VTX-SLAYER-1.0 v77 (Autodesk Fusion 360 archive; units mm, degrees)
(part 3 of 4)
sketch "vtx-antenna_mount" plane through (0, 0, 32) normal (0, 0, -1) x axis (1, 0, 0)
  line L1 (-21.0607, 19.5622) -> (-27.6022, 26.6869)
  curve K1 (-9.6778, 20.9358) -> (-10.9746, 20.0338)
  curve K2 (21.4163, 20.9358) -> (22.7131, 20.0338)
  line L2 (34.4732, 21.3854) -> (32.7992, 19.5622)
  curve K3 (34.4732, 21.3854) -> (34.8613, 29.5821)
  curve K4 (34.4729, 47.5027) -> (34.8613, 50.4161)
  curve K5 (34.8613, 50.4161) -> (34.4732, 58.6128)
  line L3 (32.7992, 60.4361) -> (34.4732, 58.6128)
  curve K6 (21.4163, 59.0625) -> (22.7131, 59.9644)
  curve K7 (-9.6778, 59.0625) -> (-10.9746, 59.9644)
  line L4 (-27.6022, 53.3114) -> (-21.0607, 60.4361)
  line L5 (26.3392, 29.4991) -> (30.319, 29.4991)
  line L6 (30.319, 32.4991) -> (26.3392, 32.4991)
  line L7 (30.319, 50.4991) -> (26.3392, 50.4991)
  line L8 (26.3392, 47.4991) -> (30.319, 47.4991)
  line L9 (30.319, 29.4991) -> (26.3392, 29.4991)
  line L10 (26.3392, 32.4991) -> (30.319, 32.4991)
  line L11 (30.319, 47.4991) -> (26.3392, 47.4991)
  line L12 (26.3392, 50.4991) -> (30.319, 50.4991)
  curve K8 (34.47, 47.4768) -> (31.9524, 44.1894)
  curve K9 (34.4729, 47.5027) -> (34.8613, 50.4161)
  curve K10 (34.8613, 50.4161) -> (34.4732, 58.6128)
  line L13 (34.4732, 58.6128) -> (32.7992, 60.4361)
  curve K11 (22.7131, 59.9644) -> (21.4163, 59.0625)
  curve K12 (34.4732, 21.3854) -> (34.8613, 29.5821)
  line L14 (32.7992, 19.5622) -> (34.4732, 21.3854)
  curve K13 (21.4163, 20.9358) -> (22.7131, 20.0338)
  line L15 (19.3693, 59.1611) -> (19.3693, 25.3947)
  line L16 (42, 39.9991) -> (17.9297, 39.9991)
  line L17 (34.47, 32.5215) -> (34.47, 47.4768)
  line L18 (34.47, 47.4768) -> (34.6901, 56.5235)
  line L19 (34.47, 32.5215) -> (34.6901, 23.4747)
  curve K14 (5.8693, 25.0204) -> (-1.6863, 24.3869)
  curve K15 (5.8693, 54.9778) -> (-1.6863, 55.6114)
  curve K16 (-13.7829, 18.3445) -> (-21.0607, 19.5622)
  curve K17 (-10.9746, 20.0338) -> (-13.7829, 18.3445)
  curve K18 (5.8693, 25.0204) -> (13.4249, 24.3869)
  curve K19 (22.7131, 20.0338) -> (25.5215, 18.3445)
  curve K20 (32.7992, 19.5622) -> (25.5215, 18.3445)
  curve K21 (32.7992, 60.4361) -> (25.5215, 61.6537)
  curve K22 (22.7131, 59.9644) -> (25.5215, 61.6537)
  curve K23 (5.8693, 54.9778) -> (13.4249, 55.6114)
  curve K24 (-10.9746, 59.9644) -> (-13.7829, 61.6537)
  curve K25 (-13.7829, 61.6537) -> (-21.0607, 60.4361)
  curve K26 (-13.7829, 18.3445) -> (-10.9746, 20.0338)
  curve K27 (25.5215, 18.3445) -> (32.7992, 19.5622)
  curve K28 (-9.4692, 21.0728) -> (-9.6778, 20.9358)
  curve K29 (-1.6863, 24.3869) -> (-1.7709, 24.37)
  curve K30 (13.4249, 24.3869) -> (13.5094, 24.37)
  curve K31 (21.2077, 21.0728) -> (21.4163, 20.9358)
  curve K32 (21.2077, 58.9255) -> (21.4163, 59.0625)
  curve K33 (13.4249, 55.6114) -> (13.5094, 55.6283)
  curve K34 (-1.6863, 55.6114) -> (-1.7709, 55.6283)
  curve K35 (-9.4692, 58.9255) -> (-9.6778, 59.0625)
  curve K36 (34.4729, 32.4955) -> (34.8613, 29.5821)
  curve K37 (34.47, 32.5215) -> (31.9524, 35.8089)
  line L20 (24.7082, 44.5019) -> (21.9057, 47.2714)
  line L21 (26.1937, 39.0527) -> (26.1937, 40.9455)
  line L22 (21.9057, 32.7269) -> (24.7082, 35.4963)
  line L23 (2.0745, 29.0204) -> (9.5861, 29.0204)
  line L24 (9.5861, 50.9778) -> (2.0745, 50.9778)
  curve K38 (-1.7709, 24.37) -> (-9.4692, 21.0728)
  curve K39 (13.5094, 24.37) -> (21.2077, 21.0728)
  line L25 (34.4729, 32.4955) -> (34.47, 32.5215)
  line L26 (34.47, 47.4768) -> (34.4729, 47.5027)
  curve K40 (13.5094, 55.6283) -> (21.2077, 58.9255)
  curve K41 (-1.7709, 55.6283) -> (-9.4692, 58.9255)
  line L27 (-9.3955, 28.8599) -> (-15.7249, 35.138)
  line L28 (10.9945, 32.4404) -> (7.2082, 36.196)
  line L29 (4.3798, 36.1845) -> (0.6546, 32.4289)
  line L30 (7.2082, 43.8022) -> (10.9945, 47.5578)
  line L31 (0.6546, 47.5694) -> (4.3798, 43.8137)
  line L32 (-3.666, 33.753) -> (-0.2646, 37.1822)
  line L33 (-12.0826, 37.1592) -> (-8.5664, 33.6715)
  line L34 (-8.5664, 46.3268) -> (-12.0826, 42.839)
  line L35 (-0.2646, 42.816) -> (-3.666, 46.2452)
  line L36 (15.3511, 46.2451) -> (11.9172, 42.839)
  line L37 (11.9172, 37.1592) -> (15.3511, 33.7531)
  line L38 (-15.7249, 44.8602) -> (-9.3955, 51.1383)
  arc A1 centre (-25.3924, 51.2824) radius 3 clockwise from (-26.8824, 48.6786) to (-27.6022, 53.3114)
  arc A2 centre (-31.849, 39.9991) radius 10 clockwise from (-26.8824, 48.6786) to (-26.8824, 31.3197)
  arc A3 centre (-25.3924, 28.7158) radius 3 clockwise from (-27.6022, 26.6869) to (-26.8824, 31.3197)
  circle C1 centre (-18.1307, 23.4991) radius 1.55
  circle C2 centre (-18.1307, 56.4991) radius 1.55
  arc A4 centre (26.3392, 30.9991) radius 1.5 clockwise from (26.3392, 29.4991) to (26.3392, 32.4991)
  arc A5 centre (30.319, 30.9991) radius 1.5 clockwise from (30.319, 32.4991) to (30.319, 29.4991)
  arc A6 centre (30.319, 48.9991) radius 1.5 clockwise from (30.319, 50.4991) to (30.319, 47.4991)
  arc A7 centre (26.3392, 48.9991) radius 1.5 clockwise from (26.3392, 47.4991) to (26.3392, 50.4991)
  arc A8 centre (26.3392, 30.9991) radius 1.5 clockwise from (26.3392, 29.4991) to (26.3392, 32.4991)
  arc A9 centre (30.319, 30.9991) radius 1.5 clockwise from (30.319, 32.4991) to (30.319, 29.4991)
  arc A10 centre (26.3392, 48.9991) radius 1.5 clockwise from (26.3392, 47.4991) to (26.3392, 50.4991)
  arc A11 centre (30.319, 48.9991) radius 1.5 clockwise from (30.319, 50.4991) to (30.319, 47.4991)
  arc A12 centre (33.5931, 39.9991) radius 4.5 clockwise from (31.9524, 35.8089) to (31.9524, 44.1894)
  circle C3 centre (29.8693, 56.4991) radius 4.8209
  circle C4 centre (29.8693, 56.4991) radius 3.025
  circle C5 centre (29.8693, 23.4991) radius 4.8209
  circle C6 centre (29.8693, 23.4991) radius 3.025
  arc A13 centre (50.9984, 39.9992) radius 31.6291 clockwise from (26.0429, 20.5666) to (26.0525, 59.4441)
  circle C7 centre (29.8693, 56.4991) radius 1.55
  circle C8 centre (29.8693, 23.4991) radius 1.55
  circle C9 centre (15.8693, 49.9991) radius 1.05
  circle C10 centre (-4.1307, 49.9991) radius 1.05
  circle C11 centre (15.8693, 29.9991) radius 1.05
  circle C12 centre (-4.1307, 29.9991) radius 1.05
  arc A14 centre (15.8693, 29.9991) radius 3.25 clockwise from (16.4204, 33.202) to (17.9117, 32.5272)
  arc A15 centre (-4.1307, 29.9991) radius 3.25 clockwise from (-5.3387, 33.0163) to (-4.7221, 33.1949)
  arc A16 centre (-18.1307, 23.4991) radius 5.55 clockwise from (-18.4728, 29.0386) to (-13.5782, 26.6736)
  arc A17 centre (-31.849, 39.9991) radius 14 clockwise from (-18.9728, 34.5032) to (-20.2526, 32.1553)
  arc A18 centre (-18.1307, 56.4991) radius 5.55 clockwise from (-13.5782, 53.3246) to (-18.4728, 50.9597)
  arc A19 centre (-4.1307, 49.9991) radius 3.25 clockwise from (-4.7221, 46.8034) to (-5.3387, 46.9819)
  arc A20 centre (15.8693, 49.9991) radius 3.25 clockwise from (17.9117, 47.4711) to (16.4204, 46.7962)
  arc A21 centre (-10.8039, 27.4399) radius 2 clockwise from (-9.3955, 28.8599) to (-10.177, 25.5408)
  arc A22 centre (-11.1174, 28.3895) radius 3 clockwise from (-10.177, 25.5408) to (-13.5782, 26.6736)
  arc A23 centre (-18.596, 31.0348) radius 2 clockwise from (-18.4728, 29.0386) to (-20.2526, 32.1553)
  arc A24 centre (-17.1334, 33.7181) radius 2 clockwise from (-18.9728, 34.5032) to (-15.7249, 35.138)
  arc A25 centre (9.5861, 31.0204) radius 2 clockwise from (10.9945, 32.4404) to (9.5861, 29.0204)
  arc A26 centre (2.0745, 31.0204) radius 2 clockwise from (2.0745, 29.0204) to (0.6546, 32.4289)
  arc A27 centre (5.7998, 34.7761) radius 2 clockwise from (4.3798, 36.1845) to (7.2082, 36.196)
  arc A28 centre (2.0745, 48.9778) radius 2 clockwise from (0.6546, 47.5694) to (2.0745, 50.9778)
  arc A29 centre (9.5861, 48.9778) radius 2 clockwise from (9.5861, 50.9778) to (10.9945, 47.5578)
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  point P53 (34.47, 47.4768)
  point P68 (34.47, 47.4768)
  point P71 (34.6901, 56.5235)
  point P72 (34.47, 47.4768)
  point P75 (34.6901, 23.4747)
  point P76 (34.47, 32.5215)
  point P78 (26.0429, 20.5666)
  point P77 (26.0525, 59.4441)
  perpendicular L15 L16
  coincident P53 P68
  tangent L3 C3
  coincident C3 P71
  coincident P53 P72
  symmetric L16 C3 C5
  symmetric L16 C4 C6
  symmetric L16 P71 P75
  symmetric L16 P72 P76
  tangent L15 A13
  coincident C5 P78
  coincident C3 P77
  dimension "d1057" diameter C4 = 6.05
work_plane "WorkPlane15" RotateAngle -45
sketch "vtx-antenna-hole" plane through (20.4594, -39.9991, 30.9099) normal (0.7071, 0, 0.7071) x axis (0, -1, 0)
  line L1 (0, 25) -> (0, -3.5)
  circle C1 centre (0, 11.4101) radius 4.5
  circle C2 centre (0, 11.4101) radius 2.5
  concentric C1 C2
  vertical L1
  dimension "d882" diameter C1 = 9
  dimension "d883" diameter C2 = 5
extrude "Extrude127" new body sketch "vtx-antenna-hole" profile of C1 C2 along normal blind 25 bodies "vtx-antenna-mount"
extrude "Extrude128" add sketch "vtx-antenna_mount" along normal blind 3
extrude "Extrude129" cut sketch "vtx-antenna-hole" profile of C2 along normal blind 47
work_plane "WorkPlane18" RotateAngle -90
sketch "Sketch92" plane through (19.3693, -39.9991, 29) normal (1, 0, 0) x axis (0, 1, 0)
  line L1 (-6.5, 0) -> (6.5, 0)
  line L2 (-6.5, -10.2079) -> (-6.5, 0)
  line L3 (6.5, -10.2079) -> (-6.5, -10.2079)
  line L4 (6.5, 0) -> (6.5, -10.2079)
  line L5 (-8.0736, 0) -> (-19.445, 0)
  line L6 (19.4325, 0) -> (8.0736, 0)
  horizontal L1
  vertical L2
  horizontal L3
  vertical L4
extrude "Extrude130" cut sketch "Sketch92" profile of L1 L2 L3 L4 along normal blind 29
fillet "Fillet99" radius 0.8
fillet "Fillet100" radius 4
fillet "Fillet101" radius 0.7
fillet "Fillet108" radius 3
fillet "Fillet109" radius 7
sketch "Sketch93" plane through (0, 0, 29) normal (0, 0, -1) x axis (1, 0, 0)
  line L1 (26.3392, 47.4991) -> (30.319, 47.4991)
  line L2 (30.319, 50.4991) -> (26.3392, 50.4991)
  line L3 (34.47, 47.4768) -> (34.47, 47.2361)
  line L4 (34.4729, 47.5027) -> (34.47, 47.4768)
  curve K1 (34.8613, 50.4161) -> (34.4729, 47.5027)
  curve K2 (34.4732, 58.6128) -> (34.8613, 50.4161)
  line L5 (33.4204, 59.7595) -> (34.4732, 58.6128)
  line L6 (24.7082, 44.5019) -> (23.7608, 45.4381)
  line L7 (26.1937, 39.0527) -> (26.1937, 40.9455)
  line L8 (23.7609, 34.5602) -> (24.7082, 35.4963)
  line L9 (34.4732, 21.3854) -> (33.4204, 20.2387)
  curve K3 (34.8613, 29.5821) -> (34.4732, 21.3854)
  curve K4 (34.4729, 32.4955) -> (34.8613, 29.5821)
  line L10 (34.47, 32.5215) -> (34.4729, 32.4955)
  line L11 (34.47, 32.7621) -> (34.47, 32.5215)
  line L12 (26.3392, 29.4991) -> (30.319, 29.4991)
  line L13 (30.319, 32.4991) -> (26.3392, 32.4991)
  curve K5 (34.47, 32.7621) -> (36.774, 35.7482)
  curve K6 (36.774, 44.25) -> (34.47, 47.2361)
  arc A1 centre (29.8693, 56.4991) radius 4.8209 clockwise from (26.0525, 59.4441) to (33.4204, 59.7595)
  arc A2 centre (19.5063, 39.9991) radius 7.6719 clockwise from (20.3034, 47.6295) to (20.3035, 32.3688)
  closed curve K7 centre (35.4859, 39.9991)
  arc A3 centre (30.319, 48.9991) radius 1.5 clockwise from (30.319, 50.4991) to (30.319, 47.4991)
  arc A4 centre (26.3392, 48.9991) radius 1.5 clockwise from (26.3392, 47.4991) to (26.3392, 50.4991)
  circle C1 centre (29.8693, 56.4991) radius 3.025
  arc A5 centre (50.9984, 39.9992) radius 31.6291 clockwise from (26.0429, 20.5666) to (22.3382, 26.6202)
  arc A6 centre (21.1937, 40.9455) radius 5 clockwise from (24.7082, 44.5019) to (26.1937, 40.9455)
  arc A7 centre (21.1937, 39.0527) radius 5 clockwise from (26.1937, 39.0527) to (24.7082, 35.4963)
  arc A8 centre (29.8693, 23.4991) radius 4.8209 clockwise from (33.4204, 20.2387) to (26.0429, 20.5666)
  closed curve K8 centre (34.6859, 39.9991)
  circle C2 centre (29.8693, 23.4991) radius 3.025
  arc A9 centre (30.319, 30.9991) radius 1.5 clockwise from (30.319, 32.4991) to (30.319, 29.4991)
  arc A10 centre (26.3392, 30.9991) radius 1.5 clockwise from (26.3392, 29.4991) to (26.3392, 32.4991)
  arc A11 centre (28.6812, 29.5812) radius 7 clockwise from (22.3382, 26.6202) to (23.7609, 34.5602)
  arc A12 centre (50.9984, 39.9992) radius 31.6291 clockwise from (22.3382, 53.3781) to (26.0525, 59.4441)
  arc A13 centre (28.6811, 50.4171) radius 7 clockwise from (23.7608, 45.4381) to (22.3382, 53.3781)
sketch "25.6 mount" plane through (0, 0, 7) normal (0, 0, 1) x axis (-1, 0, 0)
  curve K1 (2.0117, 48.6726) -> (-5.8693, 49.9885)
  curve K2 (11.053, 39.9991) -> (5.0002, 47.6552)
  curve K3 (5.0002, 32.3431) -> (11.053, 39.9991)
  curve K4 (-5.8693, 30.0098) -> (2.0117, 31.3257)
  curve K5 (-13.7502, 31.3257) -> (-5.8693, 30.0098)
  curve K6 (-15.8119, 47.4998) -> (-15.9266, 32.4985)
  curve K7 (-5.8693, 49.9885) -> (-13.7502, 48.6726)
  curve K8 (-34.4732, 21.3854) -> (-34.8613, 29.5821)
  line L1 (-32.7992, 19.5622) -> (-34.4732, 21.3854)
  curve K9 (-32.7992, 19.5622) -> (-25.5215, 18.3445)
  curve K10 (-22.7131, 20.0338) -> (-25.5215, 18.3445)
  curve K11 (-21.4163, 20.9358) -> (-22.7131, 20.0338)
  curve K12 (-21.2077, 21.0728) -> (-21.4163, 20.9358)
  curve K13 (-13.5094, 24.37) -> (-21.2077, 21.0728)
  curve K14 (-13.4249, 24.3869) -> (-13.5094, 24.37)
  curve K15 (-5.8693, 25.0204) -> (-13.4249, 24.3869)
  curve K16 (-5.8693, 25.0204) -> (1.6863, 24.3869)
  curve K17 (1.6863, 24.3869) -> (1.7709, 24.37)
  curve K18 (9.4692, 21.0728) -> (1.7709, 24.37)
  curve K19 (9.4692, 21.0728) -> (9.6778, 20.9358)
  curve K20 (9.6778, 20.9358) -> (10.9746, 20.0338)
  curve K21 (10.9746, 20.0338) -> (13.7829, 18.3445)
  curve K22 (13.7829, 18.3445) -> (21.0607, 19.5622)
  line L2 (21.7601, 20.324) -> (21.0607, 19.5622)
  curve K23 (23.3399, 24.4614) -> (21.2218, 28.4813)
  curve K24 (14.991, 38.4401) -> (21.2218, 28.4813)
  curve K25 (14.9178, 39.9991) -> (14.991, 38.4401)
  curve K26 (14.9178, 39.9991) -> (14.991, 41.5582)
  curve K27 (14.991, 41.5582) -> (21.2218, 51.5169)
  curve K28 (21.2218, 51.5169) -> (23.3399, 55.5369)
  line L3 (21.0607, 60.4361) -> (21.7601, 59.6743)
  curve K29 (13.7829, 61.6537) -> (21.0607, 60.4361)
  curve K30 (10.9746, 59.9644) -> (13.7829, 61.6537)
  curve K31 (9.6778, 59.0625) -> (10.9746, 59.9644)
  curve K32 (9.4692, 58.9255) -> (9.6778, 59.0625)
  curve K33 (1.7709, 55.6283) -> (9.4692, 58.9255)
  curve K34 (1.6863, 55.6114) -> (1.7709, 55.6283)
  curve K35 (-5.8693, 54.9778) -> (1.6863, 55.6114)
  curve K36 (-5.8693, 54.9778) -> (-13.4249, 55.6114)
  curve K37 (-13.4249, 55.6114) -> (-13.5094, 55.6283)
  curve K38 (-21.2077, 58.9255) -> (-13.5094, 55.6283)
  curve K39 (-21.2077, 58.9255) -> (-21.4163, 59.0625)
  curve K40 (-21.4163, 59.0625) -> (-22.7131, 59.9644)
  curve K41 (-22.7131, 59.9644) -> (-25.5215, 61.6537)
  curve K42 (-32.7992, 60.4361) -> (-25.5215, 61.6537)
  line L4 (-34.4732, 58.6128) -> (-32.7992, 60.4361)
  curve K43 (-34.8613, 50.4161) -> (-34.4732, 58.6128)
  curve K44 (-34.4729, 47.5027) -> (-34.8613, 50.4161)
  curve K45 (-34.2161, 44.4991) -> (-34.4729, 47.5027)
  curve K46 (-34.0919, 41.4991) -> (-34.2161, 44.4991)
  curve K47 (-34.0692, 39.9991) -> (-34.0919, 41.4991)
  curve K48 (-34.0919, 38.4991) -> (-34.0692, 39.9991)
  curve K49 (-34.0919, 38.4991) -> (-34.2161, 35.4991)
  curve K50 (-34.4729, 32.4955) -> (-34.2161, 35.4991)
  curve K51 (-34.4729, 32.4955) -> (-34.8613, 29.5821)
  line L5 (-26.3392, 32.4991) -> (-30.319, 32.4991)
  line L6 (-30.319, 29.4991) -> (-26.3392, 29.4991)
  line L7 (-23.7522, 38.4991) -> (-30.319, 38.4991)
  line L8 (-30.319, 35.4991) -> (-23.7522, 35.4991)
  line L9 (-26.3392, 50.4991) -> (-30.319, 50.4991)
  line L10 (-30.319, 47.4991) -> (-26.3392, 47.4991)
  line L11 (-23.7522, 44.4991) -> (-30.319, 44.4991)
  line L12 (-30.319, 41.4991) -> (-23.7522, 41.4991)
  line L13 (-15.8693, 49.9991) -> (4.1307, 29.9991)
  line L14 (-15.8693, 29.9991) -> (4.1307, 49.9991)
  line L15 (-5.8693, 9.9991) -> (-5.8693, 39.9991)
  line L16 (-35.8693, 39.9991) -> (-5.8693, 39.9991)
  line L17 (-5.8693, 69.9991) -> (-5.8693, 39.9991)
  line L18 (24.1307, 39.9991) -> (-5.8693, 39.9991)
  line L19 (-23.9712, 39.9991) -> (-5.8693, 58.1011)
  line L20 (-5.8693, 21.8972) -> (-23.9712, 39.9991)
  line L21 (-5.8693, 21.8972) -> (12.2327, 39.9991)
  line L22 (0.3923, 24.6107) -> (-4.104, 20.127)
  line L23 (-12.109, 24.6139) -> (-7.6395, 20.1319)
  line L24 (0.3923, 55.3876) -> (-4.104, 59.8713)
  line L25 (-12.109, 55.3843) -> (-7.6395, 59.8663)
  arc A1 centre (4.1307, 49.9991) radius 2.5 clockwise from (5.0002, 47.6552) to (2.0117, 48.6726)
  arc A2 centre (4.1307, 29.9991) radius 2.5 clockwise from (2.0117, 31.3257) to (5.0002, 32.3431)
  arc A3 centre (-15.8693, 29.9991) radius 2.5 clockwise from (-15.9266, 32.4985) to (-13.7502, 31.3257)
  arc A4 centre (-15.8693, 49.9991) radius 2.5 clockwise from (-13.7502, 48.6726) to (-15.8119, 47.4998)
  arc A5 centre (17.3404, 24.3819) radius 6 clockwise from (23.3399, 24.4614) to (21.7601, 20.324)
  arc A6 centre (17.3404, 55.6164) radius 6 clockwise from (21.7601, 59.6743) to (23.3399, 55.5369)
  arc A7 centre (-30.319, 30.9991) radius 1.5 clockwise from (-30.319, 29.4991) to (-30.319, 32.4991)
  arc A8 centre (-26.3392, 30.9991) radius 1.5 clockwise from (-26.3392, 32.4991) to (-26.3392, 29.4991)
  arc A9 centre (-23.7522, 36.9991) radius 1.5 clockwise from (-23.7522, 38.4991) to (-23.7522, 35.4991)
  arc A10 centre (-30.319, 36.9991) radius 1.5 clockwise from (-30.319, 35.4991) to (-30.319, 38.4991)
  arc A11 centre (-26.3392, 48.9991) radius 1.5 clockwise from (-26.3392, 50.4991) to (-26.3392, 47.4991)
  arc A12 centre (-30.319, 48.9991) radius 1.5 clockwise from (-30.319, 47.4991) to (-30.319, 50.4991)
  circle C1 centre (-29.8693, 56.4991) radius 2.55
  circle C2 centre (18.1307, 56.4991) radius 2.55
  circle C3 centre (-29.8693, 23.4991) radius 2.55
  circle C4 centre (18.1307, 23.4991) radius 2.55
  circle C5 centre (4.1307, 49.9991) radius 1.05
  circle C6 centre (-15.8693, 49.9991) radius 1.05
  circle C7 centre (4.1307, 29.9991) radius 1.05
  circle C8 centre (-15.8693, 29.9991) radius 1.05
  arc A13 centre (-30.319, 42.9991) radius 1.5 clockwise from (-30.319, 41.4991) to (-30.319, 44.4991)
  arc A14 centre (-23.7522, 42.9991) radius 1.5 clockwise from (-23.7522, 44.4991) to (-23.7522, 41.4991)
  circle C9 centre (-5.8693, 21.8972) radius 1.05
  circle C10 centre (-5.8693, 58.1011) radius 1.05
  circle C11 centre (12.2327, 39.9991) radius 1.05
  circle C12 centre (-23.9712, 39.9991) radius 1.05
  circle C13 centre (-5.8693, 21.8972) radius 2.5
  circle C14 centre (-5.8693, 58.1011) radius 2.5
  circle C15 centre (12.2327, 39.9991) radius 4
  circle C16 centre (-23.9712, 39.9991) radius 4
  circle C17 centre (-28.581, 42.9991) radius 1.5
  circle C18 centre (-28.581, 36.9991) radius 1.5
  point P9 (4.1307, 29.9991)
  point P97 (4.1307, 29.9991)
  point P16 (-15.8693, 49.9991)
  point P98 (-15.8693, 49.9991)
  point P5 (4.1307, 49.9991)
  point P99 (4.1307, 49.9991)
  point P13 (-15.8693, 29.9991)
  point P100 (-15.8693, 29.9991)
  point P101 (-5.8693, 39.9991)
  point P106 (-5.8693, 21.8972)
  point P107 (-5.8693, 58.1011)
  point P108 (12.2327, 39.9991)
  point P109 (-23.9712, 39.9991)
  point P110 (-5.8693, 58.1011)
  point P111 (-23.9712, 39.9991)
  point P112 (-23.9712, 39.9991)
  point P113 (-5.8693, 21.8972)
  point P114 (12.2327, 39.9991)
  point P115 (-5.8693, 21.8972)
  point P118 (-23.9712, 39.9991)
  point P121 (-4.104, 20.127)
  point P122 (0.3923, 24.6107)
  point P123 (-7.6395, 20.1319)
  point P124 (-12.109, 24.6139)
  point P125 (-4.104, 59.8713)
  point P126 (0.3923, 55.3876)
  point P127 (-7.6395, 59.8663)
  point P128 (-12.109, 55.3843)
  point P119 (-28.581, 42.9991)
  point P120 (-28.581, 36.9991)
  coincident P9 P97
  coincident P16 P98
  coincident P5 P99
  coincident P13 P100
  midpoint L14 P101
  vertical L15
  perpendicular L15 L16
  perpendicular L16 L17
  perpendicular L15 L18
  coincident L15 P106
  coincident L17 P107
  coincident L18 P108
  coincident L16 P109
  coincident P107 P110
  coincident P109 P111
  coincident P109 P112
  coincident P106 P113
  coincident P108 P114
  coincident P113 P115
  concentric C10 C14
  concentric C11 C15
  coincident P111 P118
  tangent L11 C17
  tangent L8 C18
  coincident C13 P121
  coincident K16 P122
  tangent C13 L22
  coincident C13 P123
  coincident K15 P124
  tangent C13 L23
  perpendicular L22 L23
  symmetric L16 P121 P125
  symmetric L16 P122 P126
  symmetric L16 P123 P127
  symmetric L16 P124 P128
  tangent L7 C18
  tangent L12 C17
  vertical P119 P120
  tangent C16 C18
  dimension "d1130" diameter C9 = 2.1
  dimension "d1131" diameter C10 = 2.1
  dimension "d1132" diameter C11 = 2.1
  dimension "d1133" diameter C12 = 2.1
  dimension "d1138" distance P107 P109 = 25.6
  dimension "d1139" angle L17 L19 = 45
  dimension "d1140" distance P106 P109 = 25.6
  dimension "d1141" distance P113 P114 = 25.6
  dimension "d1142" diameter C13 = 5
  dimension "d1143" diameter C14 = 5
  dimension "d1144" diameter C15 = 8
  dimension "d1145" diameter C16 = 8
extrude "Extrude133" cut sketch "25.6 mount" profile of C11 C12 against normal blind 6
extrude "Extrude134" add sketch "25.6 mount" profile of K2 K3 K15 K16 K24 K25 K26 K27 K35 K36 L7 A9 L8 L11 A14 L12 C9 C10 C13 C14 C15 C16 C17 C18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 against normal blind 2
extrude "Extrude135" cut sketch "25.6 mount" profile of C11 C12 against normal blind 2
fillet "Fillet110" radius 3
extrude "Extrude136" cut sketch "25.6 mount" profile of C11 C12 against normal blind 12
sketch "Sketch95" plane through (0, 0, -2) normal (0, 0, -1) x axis (1, 0, 0)
  curve K1 (32.9603, 51.5169) -> (35.0785, 55.5369)
  line L1 (32.7992, 60.4361) -> (33.4986, 59.6743)
  curve K2 (32.7992, 60.4361) -> (25.5215, 61.6537)
  curve K3 (22.7131, 59.9644) -> (25.5215, 61.6537)
  curve K4 (21.4163, 59.0625) -> (22.7131, 59.9644)
  curve K5 (13.5094, 55.6283) -> (21.4163, 59.0625)
  curve K6 (13.4249, 55.6114) -> (13.5094, 55.6283)
  curve K7 (5.8693, 54.9778) -> (13.4249, 55.6114)
  curve K8 (-1.6863, 55.6114) -> (5.8693, 54.9778)
  curve K9 (-1.7709, 55.6283) -> (-1.6863, 55.6114)
  curve K10 (-9.6778, 59.0625) -> (-1.7709, 55.6283)
  curve K11 (-10.9746, 59.9644) -> (-9.6778, 59.0625)
  curve K12 (-13.7829, 61.6537) -> (-10.9746, 59.9644)
  curve K13 (-13.7829, 61.6537) -> (-21.0607, 60.4361)
  line L2 (-32.5504, 47.922) -> (-21.0607, 60.4361)
  line L3 (-34.1307, 36.1341) -> (-34.1307, 43.8641)
  line L4 (-21.0607, 19.5622) -> (-32.5504, 32.0762)
  curve K14 (-13.7829, 18.3445) -> (-21.0607, 19.5622)
  curve K15 (-13.7829, 18.3445) -> (-10.9746, 20.0338)
  curve K16 (-10.9746, 20.0338) -> (-9.6778, 20.9358)
  curve K17 (-9.6778, 20.9358) -> (-1.7709, 24.37)
  curve K18 (-1.7709, 24.37) -> (-1.6863, 24.3869)
  curve K19 (-1.6863, 24.3869) -> (5.8693, 25.0204)
  curve K20 (5.8693, 25.0204) -> (13.4249, 24.3869)
  curve K21 (13.4249, 24.3869) -> (13.5094, 24.37)
  curve K22 (13.5094, 24.37) -> (21.4163, 20.9358)
  curve K23 (21.4163, 20.9358) -> (22.7131, 20.0338)
  curve K24 (22.7131, 20.0338) -> (25.5215, 18.3445)
  curve K25 (32.7992, 19.5622) -> (25.5215, 18.3445)
  line L5 (33.4986, 20.324) -> (32.7992, 19.5622)
  curve K26 (35.0785, 24.4614) -> (32.9603, 28.4813)
  curve K27 (32.9603, 28.4813) -> (26.7295, 38.4401)
  curve K28 (26.7295, 38.4401) -> (26.6564, 39.9991)
  curve K29 (26.7295, 41.5582) -> (26.6564, 39.9991)
  curve K30 (32.9603, 51.5169) -> (26.7295, 41.5582)
  line L6 (-14.6007, 32.4991) -> (-25.1307, 32.4991)
  line L7 (-25.1307, 29.4991) -> (-14.6007, 29.4991)
  line L8 (-29.6307, 35.4991) -> (-12.0137, 35.4991)
  line L9 (-12.0137, 38.4991) -> (-29.6307, 38.4991)
  line L10 (-12.0137, 44.4991) -> (-29.6307, 44.4991)
  line L11 (-29.6307, 41.4991) -> (-12.0137, 41.4991)
  line L12 (-25.1307, 47.4991) -> (-14.6007, 47.4991)
  line L13 (-14.6007, 50.4991) -> (-25.1307, 50.4991)
  circle C1 centre (23.9712, 39.9991) radius 1.05
  circle C2 centre (-12.2327, 39.9991) radius 1.05
  arc A1 centre (29.079, 55.6164) radius 6 clockwise from (33.4986, 59.6743) to (35.0785, 55.5369)
  arc A2 centre (-28.1307, 43.8641) radius 6 clockwise from (-34.1307, 43.8641) to (-32.5504, 47.922)
  arc A3 centre (-28.1307, 36.1341) radius 6 clockwise from (-32.5504, 32.0762) to (-34.1307, 36.1341)
  arc A4 centre (29.079, 24.3819) radius 6 clockwise from (35.0785, 24.4614) to (33.4986, 20.324)
  circle C3 centre (29.8693, 23.4991) radius 1.55
  arc A5 centre (15.8693, 29.9991) radius 2.1 clockwise from (15.8711, 32.0991) to (15.8711, 27.8991)
  arc A6 centre (15.873, 29.9991) radius 2.1 clockwise from (15.8711, 27.8991) to (15.8711, 32.0991)
  circle C4 centre (-4.1307, 29.9991) radius 2.1
  circle C5 centre (-18.1307, 23.4991) radius 1.55
  arc A7 centre (-14.6007, 30.9991) radius 1.5 clockwise from (-14.6007, 32.4991) to (-14.6007, 29.4991)
  arc A8 centre (-25.1307, 30.9991) radius 1.5 clockwise from (-25.1307, 29.4991) to (-25.1307, 32.4991)
  arc A9 centre (-29.6307, 36.9991) radius 1.5 clockwise from (-29.6307, 35.4991) to (-29.6307, 38.4991)
  arc A10 centre (-12.0137, 36.9991) radius 1.5 clockwise from (-12.0137, 38.4991) to (-12.0137, 35.4991)
  circle C6 centre (5.8693, 39.9991) radius 3
  arc A11 centre (-12.0137, 42.9991) radius 1.5 clockwise from (-12.0137, 44.4991) to (-12.0137, 41.4991)
  arc A12 centre (-29.6307, 42.9991) radius 1.5 clockwise from (-29.6307, 41.4991) to (-29.6307, 44.4991)
  arc A13 centre (-25.1307, 48.9991) radius 1.5 clockwise from (-25.1307, 47.4991) to (-25.1307, 50.4991)
  arc A14 centre (-14.6007, 48.9991) radius 1.5 clockwise from (-14.6007, 50.4991) to (-14.6007, 47.4991)
  circle C7 centre (-18.1307, 56.4991) radius 1.55
  circle C8 centre (-4.1307, 49.9991) radius 2.1
  arc A15 centre (15.8693, 49.9991) radius 2.1 clockwise from (15.8711, 52.0991) to (15.8711, 47.8991)
  arc A16 centre (15.873, 49.9991) radius 2.1 clockwise from (15.8711, 47.8991) to (15.8711, 52.0991)
  circle C9 centre (29.8693, 56.4991) radius 1.55
  circle C10 centre (-12.2327, 39.9991) radius 2.1
  circle C11 centre (23.9712, 39.9991) radius 2.1
  circle C12 centre (-12.2327, 39.9991) radius 4
  circle C13 centre (23.9712, 39.9991) radius 4
  circle C14 centre (-16.8424, 42.9991) radius 1.5
  circle C15 centre (-16.8424, 36.9991) radius 1.5
  concentric C2 C10
  concentric C1 C11
  concentric C2 C12
  concentric C11 C13
  tangent L10 C14
  tangent L11 C14
  tangent C12 C14
  tangent L9 C15
  tangent L8 C15
  tangent C12 C15
  dimension "d1156" diameter C10 = 4.2
  dimension "d1157" diameter C11 = 4.2
  dimension "d1158" diameter C12 = 8
  dimension "d1159" diameter C13 = 8
extrude "Extrude137" add sketch "Sketch95" profile of K27 K28 K29 K30 L8 L9 A10 L10 A11 L11 C10 C12 C13 C14 C15 against normal blind 2
extrude "Extrude138" cut sketch "Sketch95" profile of C1 C2 L9 A10 A11 L11 C10 C11 against normal blind 2
fillet "Fillet111" radius 3
extrude "Extrude139" add sketch "25.6 mount" profile of K2 K3 K24 K25 K26 K27 L7 A9 A14 L12 C11 C12 C15 C16 against normal blind 4
extrude "Extrude140" cut sketch "25.6 mount" profile of K2 K3 K24 K25 K26 K27 L7 A9 A14 L12 C11 C12 C15 C16 against normal blind 2
fillet "Fillet112" radius 3
component_insert "Component Insert5"
component_insert "Component Insert6"
extrude "Extrude132" new body sketch "cam-mount-base" profile of C2 C4 along normal blind 25 bodies "standoff1", "standoff2"
copy_paste_bodies "CopyPasteBodies13"
move "Move24"
component_insert "Component Insert7"
joint "Assemble6" alignAngle 0 alignOffsetX 0 alignOffsetY 0 alignOffsetZ 0
component_insert "Component Insert8"
joint "Assemble7" alignAngle 0 alignOffsetX 0 alignOffsetY 0 alignOffsetZ 0
component_insert "Component Insert9"
component_insert "Component Insert10"
joint "Assemble8" alignAngle 0 alignOffsetX 0 alignOffsetY 0 alignOffsetZ 0
joint "Assemble9" alignAngle 0 alignOffsetX 0 alignOffsetY 0 alignOffsetZ 0
component_insert "Component Insert11"
component_insert "Component Insert12"
component_insert "Component Insert13"
component_insert "Component Insert14"
component_insert "Component Insert15"
joint "Assemble14" alignAngle 0 alignOffsetX 0 alignOffsetY 0 alignOffsetZ 0
component_insert "Component Insert16"
component_insert "Component Insert17"
component_insert "Component Insert18"
joint "Assemble15" alignAngle 0 alignOffsetX 0 alignOffsetY 0 alignOffsetZ 0
joint "Assemble16" alignAngle 0 alignOffsetX 0 alignOffsetY 0 alignOffsetZ 0
joint "Assemble17" alignAngle 0 alignOffsetX 0 alignOffsetY 0 alignOffsetZ 0
component_insert "Component Insert19"
component_insert "Component Insert20"
joint "Assemble18" alignAngle 0 alignOffsetX 0 alignOffsetY 0 alignOffsetZ 0
joint "Assemble19" alignAngle 0 alignOffsetX 0 alignOffsetY 0 alignOffsetZ 0
component_insert "Component Insert21"
component_insert "Component Insert22"
joint "Assemble20" alignAngle 0 alignOffsetX 0 alignOffsetY 0 alignOffsetZ 0
joint "Assemble21" alignAngle 0 alignOffsetX 0 alignOffsetY 0 alignOffsetZ 0
component_insert "Component Insert23"
component_insert "Component Insert24"
component_insert "Component Insert25"
component_insert "Component Insert26"
joint "Assemble22" alignAngle 0 alignOffsetX 0 alignOffsetY 0 alignOffsetZ 0
joint "Assemble23" alignAngle 0 alignOffsetX 0 alignOffsetY 0 alignOffsetZ 0
joint "Assemble24" alignAngle 0 alignOffsetX 0 alignOffsetY 0 alignOffsetZ 0
joint "Assemble25" alignAngle 0 alignOffsetX 0 alignOffsetY 0 alignOffsetZ 0
component_insert "Component Insert27"
component_insert "Component Insert28"
component_insert "Component Insert29"
joint "Assemble26" alignAngle 0 alignOffsetX 0 alignOffsetY 0 alignOffsetZ 0
joint "Assemble27" alignAngle 0 alignOffsetX 0 alignOffsetY 0 alignOffsetZ 0
joint "Assemble28" alignAngle 0 alignOffsetX 0 alignOffsetY 0 alignOffsetZ 0
joint "Assemble29" alignAngle 0 alignOffsetX 0 alignOffsetY 0 alignOffsetZ 0
joint "Assemble30" alignAngle 0 alignOffsetX 0 alignOffsetY 0 alignOffsetZ 0
joint "Assemble31" alignAngle 0 alignOffsetX 0 alignOffsetY 0 alignOffsetZ 0
joint "Assemble32" alignAngle 0 alignOffsetX 0 alignOffsetY 0 alignOffsetZ 0
component_from_bodies "Body->Comp11"
component_from_bodies "Body->Comp12"
component_from_bodies "Body->Comp13"
component_from_bodies "Body->Comp14"
component_from_bodies "Body->Comp15"
component_from_bodies "Body->Comp16"
component_from_bodies "Body->Comp17"
component_from_bodies "Body->Comp18"
component_from_bodies "Body->Comp19"
component_from_bodies "Body->Comp21"
component_from_bodies "Body->Comp22"
component_from_bodies "Body->Comp23"
component_from_bodies "Body->Comp24"
sketch "pressnut1" plane through (0, 0, 5.9) normal (0, 0, 1) x axis (-1, 0, 0)
  circle C1 centre (-29.8693, 23.4991) radius 1.55
  circle C2 centre (-29.8693, 23.4991) radius 2.25
extrude "Extrude124" new body sketch "pressnut1" along normal blind 0.7 bodies "pressnut1"
sketch "pressnut2" plane through (0, 0, 6.6) normal (0, 0, 1) x axis (-1, 0, 0)
  line L1 (-29.6425, 21.2606) -> (-29.8656, 20.8741)
  line L2 (-29.4194, 20.8741) -> (-29.8656, 20.8741)
  line L3 (-30.0883, 21.2598) -> (-29.8656, 20.8741)
  line L4 (-29.1966, 21.352) -> (-29.3373, 20.9286)
  line L5 (-29.6331, 21.2615) -> (-29.3373, 20.9286)
  line L6 (-28.7781, 21.5314) -> (-28.8308, 21.0883)
  line L7 (-29.1875, 21.3549) -> (-28.8308, 21.0883)
  line L8 (-28.4044, 21.7913) -> (-28.3667, 21.3467)
  line L9 (-28.7698, 21.536) -> (-28.3667, 21.3467)
  line L10 (-28.0906, 22.1212) -> (-27.9642, 21.6932)
  line L11 (-28.3972, 21.7975) -> (-27.9642, 21.6932)
  line L12 (-27.8496, 22.5074) -> (-27.6397, 22.1137)
  line L13 (-28.0848, 22.1287) -> (-27.6397, 22.1137)
  line L14 (-27.6913, 22.9343) -> (-27.4064, 22.5908)
  line L15 (-27.8454, 22.516) -> (-27.4064, 22.5908)
  line L16 (-27.6222, 23.3843) -> (-27.274, 23.1052)
  line L17 (-27.6889, 22.9435) -> (-27.274, 23.1052)
  line L18 (-27.6451, 23.8389) -> (-27.2478, 23.6357)
  line L19 (-27.6217, 23.3938) -> (-27.2478, 23.6357)
  line L20 (-27.759, 24.2797) -> (-27.329, 24.1606)
  line L21 (-27.6465, 23.8483) -> (-27.329, 24.1606)
  line L22 (-27.9593, 24.6885) -> (-27.5141, 24.6584)
  line L23 (-27.7623, 24.2886) -> (-27.5141, 24.6584)
  line L24 (-28.2379, 25.0486) -> (-27.7957, 25.1088)
  line L25 (-27.9644, 24.6966) -> (-27.7957, 25.1088)
  line L26 (-28.5832, 25.3453) -> (-28.1622, 25.4932)
  line L27 (-28.2444, 25.0555) -> (-28.1622, 25.4932)
  line L28 (-28.9811, 25.5664) -> (-28.5985, 25.796)
  line L29 (-28.591, 25.3507) -> (-28.5985, 25.796)
  line L30 (-29.4155, 25.7029) -> (-29.0869, 26.0048)
  line L31 (-28.9899, 25.5702) -> (-29.0869, 26.0048)
  line L32 (-29.8684, 25.7491) -> (-29.6073, 26.111)
  line L33 (-29.4248, 25.7048) -> (-29.6073, 26.111)
  line L34 (-30.3213, 25.7032) -> (-30.1384, 26.1103)
  line L35 (-29.8779, 25.7491) -> (-30.1384, 26.1103)
  line L36 (-30.7557, 25.5671) -> (-30.6585, 26.0026)
  line L37 (-30.3306, 25.7013) -> (-30.6585, 26.0026)
  line L38 (-31.1539, 25.3463) -> (-31.1463, 25.7925)
  line L39 (-30.7645, 25.5634) -> (-31.1463, 25.7925)
  line L40 (-31.4994, 25.0499) -> (-31.5819, 25.4885)
  line L41 (-31.1617, 25.3409) -> (-31.5819, 25.4885)
  line L42 (-31.7782, 24.69) -> (-31.9473, 25.103)
  line L43 (-31.506, 25.043) -> (-31.9473, 25.103)
  line L44 (-31.9789, 24.2814) -> (-32.2276, 24.6519)
  line L45 (-31.7833, 24.682) -> (-32.2276, 24.6519)
  line L46 (-32.0932, 23.8407) -> (-32.4114, 24.1536)
  line L47 (-31.9822, 24.2725) -> (-32.4114, 24.1536)
  line L48 (-32.1164, 23.3861) -> (-32.4911, 23.6285)
  line L49 (-32.0946, 23.8313) -> (-32.4911, 23.6285)
  line L50 (-32.0477, 22.936) -> (-32.4634, 23.098)
  line L51 (-32.1159, 23.3766) -> (-32.4634, 23.098)
  line L52 (-31.8897, 22.509) -> (-32.3296, 22.5841)
  line L53 (-32.0453, 22.9268) -> (-32.3296, 22.5841)
  line L54 (-31.6491, 22.1226) -> (-32.095, 22.1075)
  line L55 (-31.8855, 22.5005) -> (-32.095, 22.1075)
  line L56 (-31.3355, 21.7925) -> (-31.7694, 21.688)
  line L57 (-31.6432, 22.1151) -> (-31.7694, 21.688)
  line L58 (-30.962, 21.5323) -> (-31.3659, 21.3425)
  line L59 (-31.3283, 21.7863) -> (-31.3659, 21.3425)
  line L60 (-30.5437, 21.3526) -> (-30.9011, 21.0854)
  line L61 (-30.9537, 21.5277) -> (-30.9011, 21.0854)
  line L62 (-30.0978, 21.2608) -> (-30.3941, 20.9271)
  line L63 (-30.5346, 21.3497) -> (-30.3941, 20.9271)
  circle C1 centre (-29.8693, 23.4991) radius 1.55
  circle C2 centre (-29.8693, 23.4991) radius 2.25
  circle C3 centre (-29.8693, 23.4991) radius 2.625
  point P4 (-29.8656, 20.8741)
  point P5 (-29.6425, 21.2606)
  point P7 (-30.0883, 21.2598)
  concentric C1 C3
  horizontal L2
  coincident C3 P4
  coincident C2 P5
  coincident C2 P7
  dimension "d1044" diameter C3 = 5.25 (= "4.500 mm + 0.75 mm")
  dimension "d1045" angle L1 L2 = 60
  dimension "d1046" angle L1 L3 = 60
  dimension "d1048" C-Pattern1-Angle = 360
extrude "Extrude125" add sketch "pressnut2" profile of C1 C2 L1 L3 L4 L5 L6 L7 L8 L9 L10 L11 L12 L13 L14 L15 L16 L17 L18 L19 L20 L21 L22 L23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 along normal blind 0.4
sketch "pressnut3" plane through (0, 0, 7) normal (0, 0, 1) x axis (-1, 0, 0)
  line L1 (-29.8656, 20.8741) -> (-30.0883, 21.2598)
  line L2 (-29.6425, 21.2606) -> (-29.8656, 20.8741)
  line L3 (-29.3373, 20.9286) -> (-29.6331, 21.2615)
  line L4 (-29.1966, 21.352) -> (-29.3373, 20.9286)
  line L5 (-28.8308, 21.0883) -> (-29.1875, 21.3549)
  line L6 (-28.7781, 21.5314) -> (-28.8308, 21.0883)
  line L7 (-28.3667, 21.3467) -> (-28.7698, 21.536)
  line L8 (-28.4044, 21.7913) -> (-28.3667, 21.3467)
  line L9 (-27.9642, 21.6932) -> (-28.3972, 21.7975)
  line L10 (-28.0906, 22.1212) -> (-27.9642, 21.6932)
  line L11 (-27.6397, 22.1137) -> (-28.0848, 22.1287)
  line L12 (-27.8496, 22.5074) -> (-27.6397, 22.1137)
  line L13 (-27.4064, 22.5908) -> (-27.8454, 22.516)
  line L14 (-27.6913, 22.9343) -> (-27.4064, 22.5908)
  line L15 (-27.274, 23.1052) -> (-27.6889, 22.9435)
  line L16 (-27.6222, 23.3843) -> (-27.274, 23.1052)
  line L17 (-27.2478, 23.6357) -> (-27.6217, 23.3938)
  line L18 (-27.6451, 23.8389) -> (-27.2478, 23.6357)
  line L19 (-27.329, 24.1606) -> (-27.6465, 23.8483)
  line L20 (-27.759, 24.2797) -> (-27.329, 24.1606)
  line L21 (-27.5141, 24.6584) -> (-27.7623, 24.2886)
  line L22 (-27.9593, 24.6885) -> (-27.5141, 24.6584)
  line L23 (-27.7957, 25.1088) -> (-27.9644, 24.6966)
  line L24 (-28.2379, 25.0486) -> (-27.7957, 25.1088)
  line L25 (-28.1622, 25.4932) -> (-28.2444, 25.0555)
  line L26 (-28.5832, 25.3453) -> (-28.1622, 25.4932)
  line L27 (-28.5985, 25.796) -> (-28.591, 25.3507)
  line L28 (-28.9811, 25.5664) -> (-28.5985, 25.796)
  line L29 (-29.0869, 26.0048) -> (-28.9899, 25.5702)
  line L30 (-29.4155, 25.7029) -> (-29.0869, 26.0048)
  line L31 (-29.6073, 26.111) -> (-29.4248, 25.7048)
  line L32 (-29.8684, 25.7491) -> (-29.6073, 26.111)
  line L33 (-30.1384, 26.1103) -> (-29.8779, 25.7491)
  line L34 (-30.3213, 25.7032) -> (-30.1384, 26.1103)
  line L35 (-30.6585, 26.0026) -> (-30.3306, 25.7013)
  line L36 (-30.7557, 25.5671) -> (-30.6585, 26.0026)
  line L37 (-31.1463, 25.7925) -> (-30.7645, 25.5634)
  line L38 (-31.1539, 25.3463) -> (-31.1463, 25.7925)
  line L39 (-31.5819, 25.4885) -> (-31.1617, 25.3409)
  line L40 (-31.4994, 25.0499) -> (-31.5819, 25.4885)
  line L41 (-31.9473, 25.103) -> (-31.506, 25.043)
  line L42 (-31.7782, 24.69) -> (-31.9473, 25.103)
  line L43 (-32.2276, 24.6519) -> (-31.7833, 24.682)
  line L44 (-31.9789, 24.2814) -> (-32.2276, 24.6519)
  line L45 (-32.4114, 24.1536) -> (-31.9822, 24.2725)
  line L46 (-32.0932, 23.8407) -> (-32.4114, 24.1536)
  line L47 (-32.4911, 23.6285) -> (-32.0946, 23.8313)
  line L48 (-32.1164, 23.3861) -> (-32.4911, 23.6285)
  line L49 (-32.4634, 23.098) -> (-32.1159, 23.3766)
  line L50 (-32.0477, 22.936) -> (-32.4634, 23.098)
  line L51 (-32.3296, 22.5841) -> (-32.0453, 22.9268)
  line L52 (-31.8897, 22.509) -> (-32.3296, 22.5841)
  line L53 (-32.095, 22.1075) -> (-31.8855, 22.5005)
  line L54 (-31.6491, 22.1226) -> (-32.095, 22.1075)
  line L55 (-31.7694, 21.688) -> (-31.6432, 22.1151)
  line L56 (-31.3355, 21.7925) -> (-31.7694, 21.688)
  line L57 (-31.3659, 21.3425) -> (-31.3283, 21.7863)
  line L58 (-30.962, 21.5323) -> (-31.3659, 21.3425)
  line L59 (-30.9011, 21.0854) -> (-30.9537, 21.5277)
  line L60 (-30.5437, 21.3526) -> (-30.9011, 21.0854)
  line L61 (-30.3941, 20.9271) -> (-30.5346, 21.3497)
  line L62 (-30.0978, 21.2608) -> (-30.3941, 20.9271)
  circle C1 centre (-29.8693, 23.4991) radius 1.55
  arc A1 centre (-29.8693, 23.4991) radius 2.25 clockwise from (-30.0883, 21.2598) to (-30.0978, 21.2608)
  arc A2 centre (-29.8693, 23.4991) radius 2.25 clockwise from (-29.6331, 21.2615) to (-29.6425, 21.2606)
  arc A3 centre (-29.8693, 23.4991) radius 2.25 clockwise from (-29.1875, 21.3549) to (-29.1966, 21.352)
  arc A4 centre (-29.8693, 23.4991) radius 2.25 clockwise from (-28.7698, 21.536) to (-28.7781, 21.5314)
  arc A5 centre (-29.8693, 23.4991) radius 2.25 clockwise from (-28.3972, 21.7975) to (-28.4044, 21.7913)
  arc A6 centre (-29.8693, 23.4991) radius 2.25 clockwise from (-28.0848, 22.1287) to (-28.0906, 22.1212)
  arc A7 centre (-29.8693, 23.4991) radius 2.25 clockwise from (-27.8454, 22.516) to (-27.8496, 22.5074)
  arc A8 centre (-29.8693, 23.4991) radius 2.25 clockwise from (-27.6889, 22.9435) to (-27.6913, 22.9343)
  arc A9 centre (-29.8693, 23.4991) radius 2.25 clockwise from (-27.6217, 23.3938) to (-27.6222, 23.3843)
  arc A10 centre (-29.8693, 23.4991) radius 2.25 clockwise from (-27.6465, 23.8483) to (-27.6451, 23.8389)
  arc A11 centre (-29.8693, 23.4991) radius 2.25 clockwise from (-27.7623, 24.2886) to (-27.759, 24.2797)
  arc A12 centre (-29.8693, 23.4991) radius 2.25 clockwise from (-27.9644, 24.6966) to (-27.9593, 24.6885)
  arc A13 centre (-29.8693, 23.4991) radius 2.25 clockwise from (-28.2444, 25.0555) to (-28.2379, 25.0486)
  arc A14 centre (-29.8693, 23.4991) radius 2.25 clockwise from (-28.591, 25.3507) to (-28.5832, 25.3453)
  arc A15 centre (-29.8693, 23.4991) radius 2.25 clockwise from (-28.9899, 25.5702) to (-28.9811, 25.5664)
  arc A16 centre (-29.8693, 23.4991) radius 2.25 clockwise from (-29.4248, 25.7048) to (-29.4155, 25.7029)
  arc A17 centre (-29.8693, 23.4991) radius 2.25 clockwise from (-29.8779, 25.7491) to (-29.8684, 25.7491)
  arc A18 centre (-29.8693, 23.4991) radius 2.25 clockwise from (-30.3306, 25.7013) to (-30.3213, 25.7032)
  arc A19 centre (-29.8693, 23.4991) radius 2.25 clockwise from (-30.7645, 25.5634) to (-30.7557, 25.5671)
  arc A20 centre (-29.8693, 23.4991) radius 2.25 clockwise from (-31.1617, 25.3409) to (-31.1539, 25.3463)
  arc A21 centre (-29.8693, 23.4991) radius 2.25 clockwise from (-31.506, 25.043) to (-31.4994, 25.0499)
  arc A22 centre (-29.8693, 23.4991) radius 2.25 clockwise from (-31.7833, 24.682) to (-31.7782, 24.69)
  arc A23 centre (-29.8693, 23.4991) radius 2.25 clockwise from (-31.9822, 24.2725) to (-31.9789, 24.2814)
  arc A24 centre (-29.8693, 23.4991) radius 2.25 clockwise from (-32.0946, 23.8313) to (-32.0932, 23.8407)
  arc A25 centre (-29.8693, 23.4991) radius 2.25 clockwise from (-32.1159, 23.3766) to (-32.1164, 23.3861)
  arc A26 centre (-29.8693, 23.4991) radius 2.25 clockwise from (-32.0453, 22.9268) to (-32.0477, 22.936)
  arc A27 centre (-29.8693, 23.4991) radius 2.25 clockwise from (-31.8855, 22.5005) to (-31.8897, 22.509)
  arc A28 centre (-29.8693, 23.4991) radius 2.25 clockwise from (-31.6432, 22.1151) to (-31.6491, 22.1226)
  arc A29 centre (-29.8693, 23.4991) radius 2.25 clockwise from (-31.3283, 21.7863) to (-31.3355, 21.7925)
  arc A30 centre (-29.8693, 23.4991) radius 2.25 clockwise from (-30.9537, 21.5277) to (-30.962, 21.5323)
  arc A31 centre (-29.8693, 23.4991) radius 2.25 clockwise from (-30.5346, 21.3497) to (-30.5437, 21.3526)
  circle C2 centre (-29.8693, 23.4991) radius 3.05
  concentric C1 C2
  dimension "d1051" diameter C2 = 6.1
extrude "Extrude126" add sketch "pressnut3" along normal blind 1.3
copy_paste_bodies "CopyPasteBodies11"
move "Move22"
copy_paste_bodies "CopyPasteBodies12"
move "Move23"
component_from_bodies "Body->Comp25"
component_from_bodies "Body->Comp26"
component_from_bodies "Body->Comp27"
component_from_bodies "Body->Comp28"
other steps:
base_feature "Base Feature1" bodies "arm-fr"
base_feature "Base Feature1" bodies "arm-rr"
base_feature "Base Feature1" bodies "pressnut1"
base_feature "Base Feature1" bodies "pressnut2"
base_feature "Base Feature1" bodies "pressnut4"
base_feature "Base Feature1" bodies "pressnut5"
base_feature "Base Feature1" bodies "arm-fl (1)"
base_feature "Base Feature1" bodies "arm-rl"
base_feature "Base Feature1" bodies "m-center"
base_feature "Base Feature1" bodies "m-bottom"
base_feature "Base Feature1" bodies "m-top"
base_feature "Base Feature1" bodies "top (1)"
base_feature "Base Feature1" bodies "cam-mount"
base_feature "Base Feature1" bodies "standoff1 (1)"
base_feature "Base Feature1" bodies "standoff2 (1)"
base_feature "Base Feature1" bodies "standoff1"
base_feature "Base Feature1" bodies "standoff2"
base_feature "Base Feature9" bodies "m-bottom", "m-top"
base_feature "Base Feature11" bodies "pressnut", "pressnut2"
base_feature "Base Feature12" bodies "pressnut (1)", "pressnut (1) (1)", "pressnut4", "pressnut5"
base_feature "Base Feature13" bodies "standoff1", "standoff2", "standoff1 (1)", "standoff2 (1)"
joint_origin "JointOrigin14"
joint_origin "JointOrigin15"
joint_origin "JointOrigin16"
joint_origin "JointOrigin17"
joint_origin "JointOrigin18"
joint_origin "JointOrigin19"
joint_origin "JointOrigin20"
joint_origin "JointOrigin21"
joint_origin "JointOrigin22"
joint_origin "JointOrigin23"
joint_origin "JointOrigin24"
joint_origin "JointOrigin25"
joint_origin "JointOrigin26"
joint_origin "JointOrigin27"
joint_origin "JointOrigin28"
joint_origin "JointOrigin29"
joint_origin "JointOrigin30"
create_component "CreateComponent11"
remove_body "RemoveBody11"
create_component "CreateComponent12"
remove_body "RemoveBody12"
create_component "CreateComponent13"
create_component "CreateComponent14"
remove_body "RemoveBody14"
create_component "CreateComponent15"
remove_body "RemoveBody15"
create_component "CreateComponent16"
remove_body "RemoveBody16"
create_component "CreateComponent17"
remove_body "RemoveBody17"
create_component "CreateComponent18"
create_component "CreateComponent19"
remove_body "RemoveBody19"
create_component "CreateComponent21"
create_component "CreateComponent22"
create_component "CreateComponent23"
create_component "CreateComponent24"
create_component "CreateComponent25"
remove_body "RemoveBody25"
create_component "CreateComponent26"
remove_body "RemoveBody26"
create_component "CreateComponent27"
remove_body "RemoveBody27"
create_component "CreateComponent28"
remove_body "RemoveBody28"
remove_body "RemoveBody29"
remove_body "RemoveBody30"
remove_body "RemoveBody31"
remove_body "RemoveBody32"
joint_origin "JointOrigin31"
joint_origin "JointOrigin32"
joint_origin "JointOrigin33"
joint_origin "JointOrigin34"
remove_body "RemoveBody33"
remove_body "RemoveBody34"
named bodies: "arm-fr", "arm-rr", "arm-rl", "m-bottom", "m-top", "m-center", "cam-mount", "pressnut1", "pressnut", "pressnut2", "pressnut (1)", "pressnut (1) (1)", "pressnut4", "pressnut5", "vtx-antenna-mount", "standoff1", "standoff2", "standoff1 (1)", "standoff2 (1)", "arm-fl", "top", "arm-fl (1)", "top (1)"

design "motor"
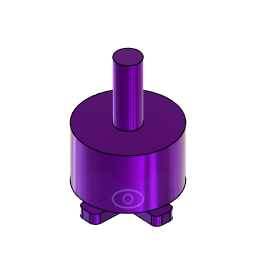
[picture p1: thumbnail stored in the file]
base_feature "Base Feature" bodies "motor (1)"
sketch "Sketch1" plane through (0, 0, 5) normal (0, 0, -1) x axis (1, 0, 0)
  line L1 (57.6027, -10.7672) -> (59.2019, -10.717)
  line L2 (59.1361, -8.618) -> (57.5368, -8.6682)
  line L3 (62.5877, -13.7451) -> (62.6725, -15.3429)
  line L4 (64.7695, -15.2315) -> (64.6847, -13.6338)
  line L5 (67.8976, -10.2308) -> (69.4855, -10.0349)
  line L6 (69.2284, -7.9507) -> (67.6404, -8.1466)
  line L7 (64.8533, -18.5431) -> (63.0539, -18.6377)
  line L8 (65.7504, -12.5921) -> (65.9888, -17.2839)
  line L9 (71.6196, -11.0848) -> (66.8861, -11.3329)
  line L10 (72.661, -8.0261) -> (72.7552, -9.8236)
  line L11 (66.6767, -7.1381) -> (71.3998, -6.8905)
  line L12 (65.1754, -1.2759) -> (65.4155, -6.0006)
  line L13 (62.0887, -0.2348) -> (63.9137, -0.1385)
  line L14 (61.2013, -6.2234) -> (60.9535, -1.4959)
  line L15 (55.3943, -7.7294) -> (60.0658, -7.4845)
  line L16 (54.353, -10.788) -> (54.2588, -8.9905)
  line L17 (60.2857, -11.6788) -> (55.6141, -11.9236)
  line L18 (61.7926, -17.5022) -> (61.5468, -12.8143)
  arc A1 centre (59.169, -9.6675) radius 1.05 clockwise from (59.1361, -8.618) to (59.2019, -10.717)
  arc A2 centre (57.5698, -9.7177) radius 1.05 clockwise from (57.6027, -10.7672) to (57.5368, -8.6682)
  arc A3 centre (63.721, -15.2872) radius 1.05 clockwise from (64.7695, -15.2315) to (62.6725, -15.3429)
  arc A4 centre (63.6362, -13.6895) radius 1.05 clockwise from (62.5877, -13.7451) to (64.6847, -13.6338)
  arc A5 centre (69.357, -8.9928) radius 1.05 clockwise from (69.2284, -7.9507) to (69.4855, -10.0349)
  arc A6 centre (67.769, -9.1887) radius 1.05 clockwise from (67.8976, -10.2308) to (67.6404, -8.1466)
  arc A7 centre (62.9909, -17.4393) radius 1.2 clockwise from (63.0539, -18.6377) to (61.7926, -17.5022)
  arc A8 centre (64.7904, -17.3448) radius 1.2 clockwise from (65.9888, -17.2839) to (64.8533, -18.5431)
  arc A9 centre (66.9489, -12.5312) radius 1.2 clockwise from (65.7504, -12.5921) to (66.8861, -11.3329)
  arc A10 centre (71.5568, -9.8864) radius 1.2 clockwise from (72.7552, -9.8236) to (71.6196, -11.0848)
  arc A11 centre (71.4626, -8.0889) radius 1.2 clockwise from (71.3998, -6.8905) to (72.661, -8.0261)
  arc A12 centre (66.6139, -5.9397) radius 1.2 clockwise from (66.6767, -7.1381) to (65.4155, -6.0006)
  arc A13 centre (63.9769, -1.3368) radius 1.2 clockwise from (63.9137, -0.1385) to (65.1754, -1.2759)
  arc A14 centre (62.1519, -1.4331) radius 1.2 clockwise from (60.9535, -1.4959) to (62.0887, -0.2348)
  arc A15 centre (60.003, -6.2862) radius 1.2 clockwise from (61.2013, -6.2234) to (60.0658, -7.4845)
  arc A16 centre (55.4571, -8.9277) radius 1.2 clockwise from (54.2588, -8.9905) to (55.3943, -7.7294)
  arc A17 centre (55.5513, -10.7252) radius 1.2 clockwise from (55.6141, -11.9236) to (54.353, -10.788)
  arc A18 centre (60.3485, -12.8771) radius 1.2 clockwise from (60.2857, -11.6788) to (61.5468, -12.8143)
  circle C1 centre (63.469, -9.3895) radius 2.5
named bodies: "motor (1)"

design "M2 screw size FLAT WASHER"
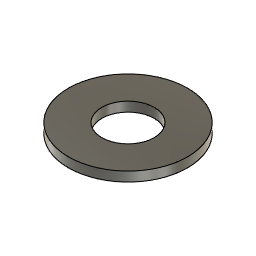
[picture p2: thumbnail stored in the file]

design "runcam_phoenix_2"
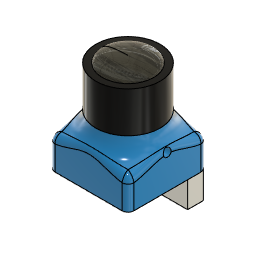
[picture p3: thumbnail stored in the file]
sketch "Skizze1" plane through (0, 0, 0) normal (0, 0, 1) x axis (1, 0, 0)
  line L1 (20, 0) -> (0, 0)
  line L2 (20, 20) -> (20, 0)
  line L3 (0, 20) -> (20, 20)
  line L4 (0, 0) -> (0, 20)
  point P1 (0, 0)
  point P2 (0, 0)
  point P3 (20, 0)
  point P5 (0, 20)
  horizontal L1
  vertical L2
  horizontal L3
  vertical L4
  coincident P1 P2
  dimension "d1" distance P2 P3 = 20
  dimension "d2" distance P2 P5 = 20
extrude "Extrusion1" new body sketch "Skizze1" along normal blind 8
sketch "Skizze2" plane through (0, 0, 8) normal (0, 0, 1) x axis (-1, 0, 0)
  line L1 (0, 0) -> (0, -20)
  line L2 (-20, 0) -> (0, 0)
  line L3 (-20, -20) -> (-20, 0)
  line L4 (0, -20) -> (-20, -20)
  circle C1 centre (-10, -10) radius 8.15
  dimension "d5" diameter C1 = 16.3
extrude "Extrusion2" add sketch "Skizze2" profile of C1 along normal blind 15.3
fillet "Abrundung1" radius 1.5
fillet "Abrundung2" radius 5
fillet "Abrundung3" radius 2
sphere_primitive "Grundkörper Kugel" Diameter 13
scale "Maßstab" ScaleZ 0.2475
split "Teilen1"
work_plane "Arbeitsebene" AlongDistance -13
split "Teilen2"
sketch "Skizze4" plane through (20, 0, 0) normal (1, 0, 0) x axis (0, 1, 0)
  curve K1 (18.5, 6.1577) -> (1.5, 6.1577)
  line L1 (1.5, 0) -> (1.5, 6.1577)
  line L2 (18.5, 0) -> (1.5, 0)
  line L3 (18.5, 6.1577) -> (18.5, 0)
  circle C1 centre (10, 8.5) radius 0.975
  point P6 (10, 8.5)
  dimension "d19" diameter C1 = 1.95
  dimension "d20" distance L2 P6 = 8.5
extrude "Extrusion3" cut sketch "Skizze4" profile of C1 against normal blind 4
